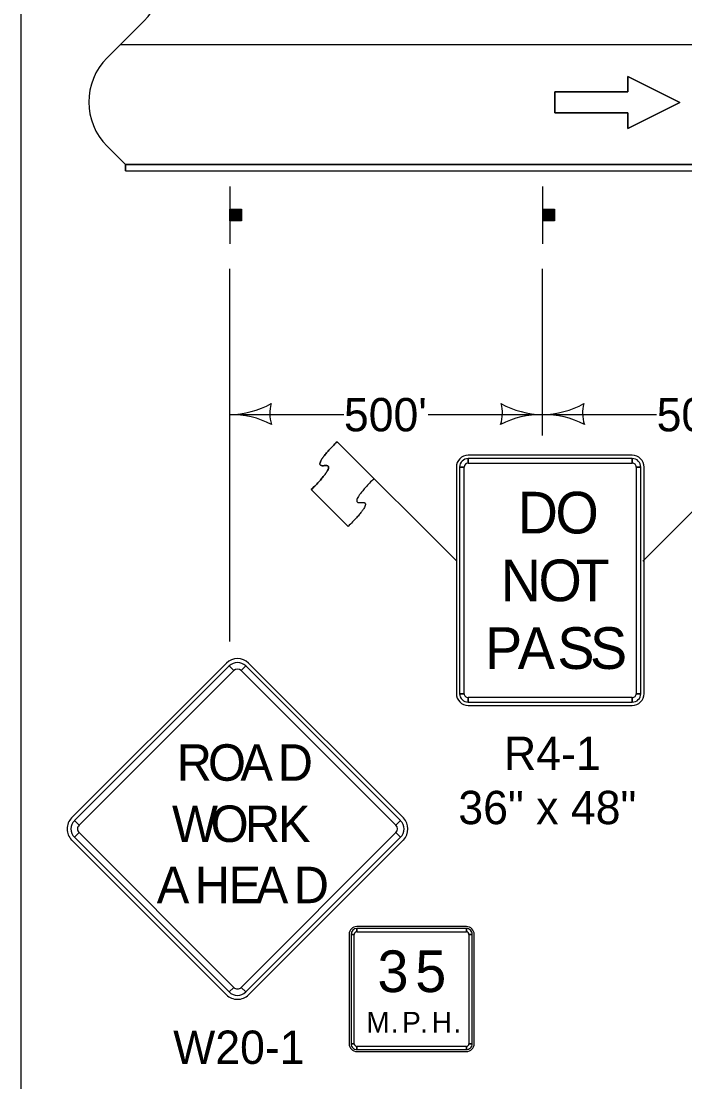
# Model space of a CAD drawing. Extents: x -2134934 to -2127057, y -2139046 to -2137036.
# Drawn here: x -2134934 to -2134616, y -2138105 to -2137596 of the extents above; entities that cross this region are included whole.
import ezdxf

# ---------------------------------------------------------------- set-up
doc = ezdxf.new("R2010")
doc.units = 0
for name, color, linetype in [('Barrier', 7, 'Continuous'), ('BridgeSuperStructureExisting', 7, 'Continuous'), ('Default', 7, 'Continuous'), ('DsnShtPlotIdentification', 7, 'Continuous'), ('TC_Barrier', 7, 'Continuous')]:
    doc.layers.add(name, color=color, linetype=linetype)

msp = doc.modelspace()

# ---------------------------------------------------------------- linework, layer by layer
at = {"layer": 'Barrier'}
for p, q in [((-2134725.6, -2137855.42), (-2134782.94, -2137798.12)), ((-2134782.94, -2137798.12), (-2134765.25, -2137815.8)), ((-2134636.31, -2137855.42), (-2134578.99, -2137798.11)), ((-2134641.36, -2137804.67), (-2134720.11, -2137804.67)), ((-2134720.11, -2137808.42), (-2134720.11, -2137806.23)), ((-2134641.36, -2137806.23), (-2134641.36, -2137808.42)), ((-2134725.73, -2137810.29), (-2134725.73, -2137919.04)), ((-2134724.17, -2137810.29), (-2134721.98, -2137810.29)), ((-2134639.48, -2137810.29), (-2134637.3, -2137810.29)), ((-2134635.73, -2137919.04), (-2134635.73, -2137810.29)), ((-2134777.63, -2137838.79), (-2134795.31, -2137821.12)), ((-2134836.02, -2137904.4), (-2134910.27, -2137978.64)), ((-2134751.17, -2137978.64), (-2134825.41, -2137904.4)), ((-2134834.69, -2137905.72), (-2134832.48, -2137907.93)), ((-2134828.95, -2137907.93), (-2134826.74, -2137905.72)), ((-2134721.98, -2137919.04), (-2134724.17, -2137919.04)), ((-2134637.3, -2137919.04), (-2134639.48, -2137919.04)), ((-2134720.11, -2137923.1), (-2134720.11, -2137920.91)), ((-2134720.11, -2137924.66), (-2134641.36, -2137924.66)), ((-2134641.36, -2137920.91), (-2134641.36, -2137923.1)), ((-2134906.73, -2137982.18), (-2134908.94, -2137979.97)), ((-2134752.49, -2137979.97), (-2134754.7, -2137982.18)), ((-2134908.94, -2137987.92), (-2134906.73, -2137985.71)), ((-2134754.7, -2137985.71), (-2134752.49, -2137987.92)), ((-2134910.27, -2137989.25), (-2134836.02, -2138063.5)), ((-2134825.41, -2138063.5), (-2134751.17, -2137989.25)), ((-2134720.95, -2138030.77), (-2134773.45, -2138030.77)), ((-2134773.45, -2138033.27), (-2134773.45, -2138031.71)), ((-2134720.95, -2138031.71), (-2134720.95, -2138033.27)), ((-2134777.2, -2138034.52), (-2134777.2, -2138087.02)), ((-2134776.26, -2138034.52), (-2134774.7, -2138034.52)), ((-2134719.7, -2138034.52), (-2134718.13, -2138034.52)), ((-2134717.2, -2138087.02), (-2134717.2, -2138034.52)), ((-2134832.48, -2138059.96), (-2134834.69, -2138062.17)), ((-2134826.74, -2138062.17), (-2134828.95, -2138059.96)), ((-2134774.7, -2138087.02), (-2134776.26, -2138087.02)), ((-2134718.13, -2138087.02), (-2134719.7, -2138087.02)), ((-2134773.45, -2138089.83), (-2134773.45, -2138088.27)), ((-2134773.45, -2138090.77), (-2134720.95, -2138090.77)), ((-2134720.95, -2138088.27), (-2134720.95, -2138089.83))]:
    msp.add_line(p, q, dxfattribs=at)
for points in [[(-2134641.36, -2137806.23), (-2134720.11, -2137806.23), (-2134720.11, -2137808.42), (-2134641.36, -2137808.42), (-2134641.36, -2137806.23)], [(-2134724.17, -2137810.29), (-2134724.17, -2137919.04), (-2134721.98, -2137919.04), (-2134721.98, -2137810.29), (-2134724.17, -2137810.29)], [(-2134637.3, -2137919.04), (-2134637.3, -2137810.29), (-2134639.48, -2137810.29), (-2134639.48, -2137919.04), (-2134637.3, -2137919.04)], [(-2134834.69, -2137905.72), (-2134908.94, -2137979.97), (-2134906.73, -2137982.18), (-2134832.48, -2137907.93), (-2134834.69, -2137905.72)], [(-2134752.49, -2137979.97), (-2134826.74, -2137905.72), (-2134828.95, -2137907.93), (-2134754.7, -2137982.18), (-2134752.49, -2137979.97)], [(-2134720.11, -2137923.1), (-2134641.36, -2137923.1), (-2134641.36, -2137920.91), (-2134720.11, -2137920.91), (-2134720.11, -2137923.1)], [(-2134908.94, -2137987.92), (-2134834.69, -2138062.17), (-2134832.48, -2138059.96), (-2134906.73, -2137985.71), (-2134908.94, -2137987.92)], [(-2134826.74, -2138062.17), (-2134752.49, -2137987.92), (-2134754.7, -2137985.71), (-2134828.95, -2138059.96), (-2134826.74, -2138062.17)], [(-2134720.95, -2138031.71), (-2134773.45, -2138031.71), (-2134773.45, -2138033.27), (-2134720.95, -2138033.27), (-2134720.95, -2138031.71)], [(-2134776.26, -2138034.52), (-2134776.26, -2138087.02), (-2134774.7, -2138087.02), (-2134774.7, -2138034.52), (-2134776.26, -2138034.52)], [(-2134718.13, -2138087.02), (-2134718.13, -2138034.52), (-2134719.7, -2138034.52), (-2134719.7, -2138087.02), (-2134718.13, -2138087.02)], [(-2134773.45, -2138089.83), (-2134720.95, -2138089.83), (-2134720.95, -2138088.27), (-2134773.45, -2138088.27), (-2134773.45, -2138089.83)]]:
    msp.add_lwpolyline(points, close=True, dxfattribs=at)
for centre, radius, start, end in [((-2134720.11, -2137810.29), 5.62, 90.0002, 179.9998), ((-2134720.11, -2137810.29), 4.06, 90.0002, 179.9998), ((-2134641.36, -2137810.29), 5.62, 0, 90.0002), ((-2134641.36, -2137810.29), 4.06, 0, 90.0002), ((-2134720.11, -2137810.29), 1.87, 90.0002, 179.9998), ((-2134641.36, -2137810.29), 1.87, 0, 90.0002), ((-2134830.72, -2137909.7), 7.5, 45, 134.9997), ((-2134830.72, -2137909.7), 5.62, 45, 134.9997), ((-2134830.72, -2137909.7), 2.5, 45, 134.9997), ((-2134720.11, -2137919.04), 5.62, 179.9998, 270.0001), ((-2134720.11, -2137919.04), 4.06, 179.9998, 270.0001), ((-2134720.11, -2137919.04), 1.87, 179.9998, 270.0001), ((-2134641.36, -2137919.04), 5.62, 270.0001, 0.0003), ((-2134641.36, -2137919.04), 4.06, 270.0001, 0.0003), ((-2134641.36, -2137919.04), 1.87, 270.0001, 0.0003), ((-2134904.96, -2137983.95), 7.5, 134.9997, 225), ((-2134904.96, -2137983.95), 5.62, 134.9997, 225), ((-2134756.47, -2137983.95), 5.62, 315.0002, 44.9998), ((-2134756.47, -2137983.95), 7.5, 315.0002, 44.9998), ((-2134904.96, -2137983.95), 2.5, 134.9997, 225), ((-2134756.47, -2137983.95), 2.5, 315.0002, 44.9998), ((-2134773.45, -2138034.52), 3.75, 90.0002, 179.9998), ((-2134773.45, -2138034.52), 2.81, 90.0002, 179.9998), ((-2134720.95, -2138034.52), 3.75, 0, 90.0002), ((-2134720.95, -2138034.52), 2.81, 0, 90.0002), ((-2134773.45, -2138034.52), 1.25, 90.0002, 179.9998), ((-2134720.95, -2138034.52), 1.25, 0, 90.0002), ((-2134830.72, -2138058.19), 5.62, 225, 315.0002), ((-2134830.72, -2138058.19), 2.5, 225, 315.0002), ((-2134830.72, -2138058.19), 7.5, 225, 315.0002), ((-2134773.45, -2138087.02), 3.75, 179.9998, 270.0001), ((-2134773.45, -2138087.02), 2.81, 179.9998, 270.0001), ((-2134773.45, -2138087.02), 1.25, 179.9998, 270.0001), ((-2134720.95, -2138087.02), 3.75, 270.0001, 0.0003), ((-2134720.95, -2138087.02), 2.81, 270.0001, 0.0003), ((-2134720.95, -2138087.02), 1.25, 270.0001, 0.0003)]:
    msp.add_arc(centre, radius, start, end, dxfattribs=at)
for points in [[(-2134795.31, -2137821.12), (-2134782.93, -2137808.74), (-2134795.31, -2137810.51), (-2134782.94, -2137798.12)], [(-2134765.25, -2137815.8), (-2134777.62, -2137828.19), (-2134765.25, -2137826.41), (-2134777.63, -2137838.79)]]:
    msp.add_open_spline(points, degree=2, dxfattribs=at)
at = {"layer": 'BridgeSuperStructureExisting'}
for p, q in [((-2134893.23, -2137613.94), (-2134875.66, -2137596.37)), ((-2134875.65, -2137596.37), (-2134893.23, -2137613.95)), ((-2134884.44, -2137665.16), (-2134893.23, -2137656.37)), ((-2134893.23, -2137656.37), (-2134884.44, -2137665.16)), ((-2134884.44, -2137665.16), (-2133384.44, -2137665.16)), ((-2134834.44, -2137675.66), (-2134834.44, -2137703.16)), ((-2134684.44, -2137675.66), (-2134684.44, -2137703.16)), ((-2134834.03, -2137692.11), (-2134834.03, -2137686.52)), ((-2134833.75, -2137686.52), (-2134833.75, -2137692.11)), ((-2134833.48, -2137692.11), (-2134833.48, -2137686.52)), ((-2134833.22, -2137686.52), (-2134833.22, -2137692.11)), ((-2134833, -2137692.11), (-2134833, -2137686.52)), ((-2134832.79, -2137686.52), (-2134832.79, -2137692.11)), ((-2134832.45, -2137692.11), (-2134832.45, -2137686.52)), ((-2134832.19, -2137686.52), (-2134832.19, -2137692.11)), ((-2134831.96, -2137692.11), (-2134831.98, -2137686.52)), ((-2134831.65, -2137686.52), (-2134831.65, -2137692.11)), ((-2134831.27, -2137692.11), (-2134831.27, -2137686.52)), ((-2134830.84, -2137686.52), (-2134830.84, -2137692.11)), ((-2134830.61, -2137692.11), (-2134830.63, -2137686.52)), ((-2134830.2, -2137686.52), (-2134830.18, -2137692.11)), ((-2134829.98, -2137692.11), (-2134829.98, -2137686.52)), ((-2134829.66, -2137686.52), (-2134829.66, -2137692.11)), ((-2134829.43, -2137692.11), (-2134829.43, -2137686.52)), ((-2134829.11, -2137686.52), (-2134829.11, -2137692.11)), ((-2134684.03, -2137692.11), (-2134684.03, -2137686.52)), ((-2134683.75, -2137686.52), (-2134683.75, -2137692.11)), ((-2134683.48, -2137692.11), (-2134683.48, -2137686.52)), ((-2134683.22, -2137686.52), (-2134683.22, -2137692.11)), ((-2134683, -2137692.11), (-2134683, -2137686.52)), ((-2134682.79, -2137686.52), (-2134682.79, -2137692.11)), ((-2134682.45, -2137692.11), (-2134682.45, -2137686.52)), ((-2134682.19, -2137686.52), (-2134682.19, -2137692.11)), ((-2134681.97, -2137692.11), (-2134681.98, -2137686.52)), ((-2134681.65, -2137686.52), (-2134681.65, -2137692.11)), ((-2134681.27, -2137692.11), (-2134681.27, -2137686.52)), ((-2134680.84, -2137686.52), (-2134680.84, -2137692.11)), ((-2134680.62, -2137692.11), (-2134680.63, -2137686.52)), ((-2134680.2, -2137686.52), (-2134680.18, -2137692.11)), ((-2134679.98, -2137692.11), (-2134679.98, -2137686.52)), ((-2134679.66, -2137686.52), (-2134679.66, -2137692.11)), ((-2134679.43, -2137692.11), (-2134679.43, -2137686.52)), ((-2134679.12, -2137686.52), (-2134679.12, -2137692.11)), ((-2134834.44, -2137893.97), (-2134834.44, -2137715.16)), ((-2134684.44, -2137795.16), (-2134684.44, -2137715.16)), ((-2134834.44, -2137785.16), (-2134779.69, -2137785.16)), ((-2134739.19, -2137785.16), (-2134684.44, -2137785.16)), ((-2134684.44, -2137785.16), (-2134629.69, -2137785.16))]:
    msp.add_line(p, q, dxfattribs=at)
for points in [[(-2134678.55, -2137630.33), (-2134678.55, -2137640.33), (-2134643.55, -2137640.33), (-2134643.55, -2137647.83), (-2134618.55, -2137635.33), (-2134643.55, -2137622.83), (-2134643.55, -2137630.33)], [(-2134834.35, -2137692.11), (-2134834.35, -2137686.48), (-2134828.72, -2137686.48), (-2134828.72, -2137692.11)], [(-2134684.35, -2137692.11), (-2134684.35, -2137686.48), (-2134678.72, -2137686.48), (-2134678.72, -2137692.11)]]:
    msp.add_lwpolyline(points, close=True, dxfattribs=at)
msp.add_lwpolyline([(-2134643.55, -2137630.33), (-2134643.55, -2137622.83), (-2134618.55, -2137635.33), (-2134643.55, -2137647.83), (-2134643.55, -2137640.33), (-2134678.55, -2137640.33), (-2134678.55, -2137630.33), (-2134643.55, -2137630.33)], dxfattribs=at)
for centre, radius, start, end in [((-2134896.87, -2137575.16), 30, 315, 45), ((-2134896.87, -2137575.16), 30, 315, 45), ((-2134872.02, -2137635.16), 30, 135, 225), ((-2134872.02, -2137635.16), 30, 135, 225), ((-2134835.2, -2137742.67), 42.5, 271.0176, 299.0725), ((-2134798.82, -2137784.54), 16.42, 163.2666, 198.7334), ((-2134720.06, -2137784.54), 16.42, 341.2666, 16.7334), ((-2134683.69, -2137742.67), 42.5, 240.9275, 268.9824), ((-2134685.2, -2137742.67), 42.5, 271.0176, 299.0725), ((-2134648.82, -2137784.54), 16.42, 163.2666, 198.7334), ((-2134833.71, -2137827.65), 42.5, 62.9275, 90.9824), ((-2134685.17, -2137827.65), 42.5, 89.0176, 117.0725), ((-2134683.71, -2137827.65), 42.5, 62.9275, 90.9824)]:
    msp.add_arc(centre, radius, start, end, dxfattribs=at)
at = {"layer": 'Default'}
msp.add_lwpolyline([(-2134934.44, -2137035.95), (-2131799.45, -2137035.95), (-2131799.45, -2139045.94), (-2134934.44, -2139045.94)], close=True, dxfattribs=at)
at = {"layer": 'DsnShtPlotIdentification'}
for p, q in [((-2134234.44, -2137607.66), (-2134886.94, -2137607.66)), ((-2134884.44, -2137665.16), (-2133384.44, -2137665.16)), ((-2134884.44, -2137665.16), (-2133384.44, -2137665.16)), ((-2134884.44, -2137668.16), (-2134884.44, -2137665.16)), ((-2134239.44, -2137665.16), (-2134884.44, -2137665.16)), ((-2134884.44, -2137665.16), (-2134884.44, -2137668.16)), ((-2134884.44, -2137668.16), (-2133384.44, -2137668.16)), ((-2134884.44, -2137668.16), (-2133384.44, -2137668.16))]:
    msp.add_line(p, q, dxfattribs=at)
at = {"layer": 'TC_Barrier'}
msp.add_line((-2134795.31, -2137821.12), (-2134777.63, -2137838.79), dxfattribs=at)
for points in [[(-2134782.94, -2137798.12), (-2134795.31, -2137810.51), (-2134782.93, -2137808.74), (-2134795.31, -2137821.12)], [(-2134765.25, -2137815.8), (-2134777.62, -2137828.19), (-2134765.25, -2137826.41), (-2134777.63, -2137838.79)]]:
    msp.add_open_spline(points, degree=2, dxfattribs=at)

# ---------------------------------------------------------------- texts
at = {"layer": 'Barrier'}
for s, height, p in [('D', 20, (-2134696.36, -2137842.17)), ('O', 20, (-2134678.23, -2137842.17)), ('N', 20, (-2134704.48, -2137874.67)), ('O', 20, (-2134686.36, -2137874.67)), ('T', 20, (-2134668.55, -2137874.67)), ('P', 20, (-2134712, -2137907.17)), ('A', 20, (-2134696.31, -2137907.17)), ('S', 20, (-2134677.34, -2137907.17)), ('S', 20, (-2134661.66, -2137907.17)), ('R4-1', 16, (-2134702.9, -2137955.66)), ('R', 17.5, (-2134859.88, -2137960.82)), ('O', 17.5, (-2134844.87, -2137960.82)), ('A', 17.5, (-2134829.32, -2137960.82)), ('D', 17.5, (-2134811.44, -2137960.82)), ('36" x 48"', 16, (-2134724.8, -2137981.66)), ('W', 17.5, (-2134862.16, -2137990.2)), ('O', 17.5, (-2134843.57, -2137990.2)), ('R', 17.5, (-2134827.16, -2137990.2)), ('K', 17.5, (-2134811.3, -2137990.2)), ('A', 17.5, (-2134869.44, -2138019.57)), ('H', 17.5, (-2134851.23, -2138019.57)), ('E', 17.5, (-2134835, -2138019.57)), ('A', 17.5, (-2134821.96, -2138019.57)), ('D', 17.5, (-2134803.75, -2138019.57)), ('3', 20, (-2134763.58, -2138062.23)), ('5', 20, (-2134745.46, -2138062.23)), ('M', 10, (-2134768.97, -2138081.71)), ('P', 10, (-2134751.72, -2138081.71)), ('H', 10, (-2134737.6, -2138081.71)), ('W20-1', 16, (-2134861.57, -2138096.69)), ('.', 10, (-2134757.18, -2138081.71)), ('.', 10, (-2134743.06, -2138081.71)), ('.', 10, (-2134727.13, -2138081.71))]:
    msp.add_text(s, height=height, dxfattribs=at).set_placement(p)
at = {"layer": 'BridgeSuperStructureExisting'}
for p in [(-2134779.69, -2137793.16), (-2134629.69, -2137793.16)]:
    msp.add_text("500'", height=16, dxfattribs=at).set_placement(p)

doc.saveas('drawing.dxf')
